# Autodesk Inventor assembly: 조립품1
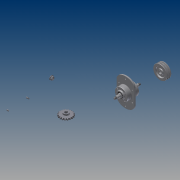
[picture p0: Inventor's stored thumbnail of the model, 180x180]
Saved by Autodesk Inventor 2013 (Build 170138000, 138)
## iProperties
Created: 2015-02
Part Number: 조립품1
Document SubType Name: Assembly
Designer: cad8
Author: cad8
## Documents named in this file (12)
- C:\Documents and Settings\cad8\바탕 화면\450208V1016\조립품1.iam
- C:\Documents and Settings\cad8\바탕 화면\450208V1016\2-커버.ipt
- C:\Documents and Settings\cad8\바탕 화면\450208V1016\3-축.ipt
- C:\Documents and Settings\cad8\바탕 화면\450208V1016\4-V벨트풀리.ipt
- C:\Documents and Settings\cad8\바탕 화면\450208V1016\5-체인 스프로킷.ipt
- C:\Documents and Settings\cad8\바탕 화면\450208V1016\6-베어링 6206.ipt
- C:\Documents and Settings\cad8\바탕 화면\450208V1016\7-부시.ipt
- C:\Documents and Settings\cad8\바탕 화면\450208V1016\8-오일실 30x42.ipt
- C:\Documents and Settings\cad8\바탕 화면\450208V1016\9-M16-너트.ipt
- C:\Documents and Settings\cad8\바탕 화면\450208V1016\10-M6.ipt
- C:\Documents and Settings\cad8\바탕 화면\450208V1016\11-키 6x6.ipt
- C:\Documents and Settings\cad8\바탕 화면\450208V1016\본체.ipt
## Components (13 placed, 10 different names)
1. 2-커버:1
2. 3-축:1
3. 4-V벨트풀리:1
4. 5-체인 스프로킷:1
5. 6-베어링 6206:1
6. 7-부시:1
7. 8-8-오일실 30x42:1
8. 9-M16 너트:1
9. 10-M6:1
10. 11-키 6x6:1
11. 6-베어링 6206:2
12. 2-커버:2
13. 8-8-오일실 30x42:2
